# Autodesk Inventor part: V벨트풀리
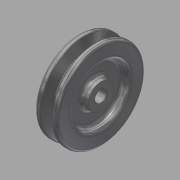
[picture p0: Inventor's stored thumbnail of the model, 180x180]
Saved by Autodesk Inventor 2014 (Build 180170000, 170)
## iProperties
Created: 2015-11
Part Number: V벨트풀리
Material: 강철, 탄소
Document SubType Name: Modeling
Designer: mduedu
Density: 7.87 g/cm^3
Mass: 415.441 g
Surface Area: 174.543 cm^2
Volume: 52.788 cm^3
Appearance: 반광택
Author: mduedu
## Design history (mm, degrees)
sketch "스케치1"
  geometry: L1 (-9.5, 0)-(9.5, 0); L2 (0, 0)-(0, 37.7); L3 (-4.825, 37.7)-(-9.5, 37.7); L4 (-9.5, 37.7)-(-9.5, 0); L5 (0, 28.7)-(-2.074, 28.7); L6 (-2.074, 28.7)-(-4.825, 37.7); L7 (4.825, 37.7)-(9.5, 37.7); L8 (9.5, 37.7)-(9.5, 0); L9 (0, 28.7)-(2.074, 28.7); L10 (2.074, 28.7)-(4.825, 37.7); L11 (-9.5, 35)-(9.5, 35); 3 further points
  constraints: 22 end point, 7 point on line, 4 perpendicular, 3 symmetric about line, 1 coincident, 1 horizontal, 1 horizontal alignment, 1 midpoint, 1 vertical
  dimensions: "d0" = 19 distance of L1.start L1.end; "d2" = 75.4 diameter of L2.end L1 (derived); "d3" = 34 deg angle of L10 L6; "d4" = 6.3 distance between parallel lines of L11 L9; "d5" = 2.7 distance between parallel lines of L7 L11; "d6" = 8 distance of point (4, 35) point (-4, 35); "d7" = 70 diameter of L11 L1
revolve "회전1" sketch "스케치1" stored, may be unused: angle "d8" = 90 deg
sketch "스케치2"
  geometry: C1 r 24 at (0, 0); C2 r 11 at (0, 0); 1 further point
  constraints: 2 centre point, 2 coincident
  dimensions: "d9" = 48 diameter of C1; "d10" = 22 diameter of C2
extrude "돌출1" cut sketch "스케치2" distance "d11" = 6; taper "d12" = 0 deg
fillet "모깎기1" dims "d13" = 3
fillet "모깎기2" dims "d14" = 3
fillet "모깎기3" dims "d15" = 1, "d16" = 0.5, "d17" = 2
hole "구멍1" diameter "d20" = 10; stored, may be unused: countersink angle "d24" = 90 deg, drill point angle "d26" = 118 deg; dims "d18" = 10, "d19" = 10, "d21" = 6, "d22" = 4, "d23" = 2, "d25" = 8
sketch "스케치3"
  geometry: L1 (-1.5, 0)-(1.5, 0); L2 (1.5, 0)-(1.5, 6.4); L3 (1.5, 6.4)-(-1.5, 6.4); L4 (-1.5, 6.4)-(-1.5, 0); 2 further points
  constraints: 8 end point, 2 parallel, 1 coincident, 1 horizontal, 1 midpoint, 1 perpendicular
  dimensions: "d27" = 3 distance of L2.end L3.end; "d29" = 6.4 distance of L3.end L1.start
extrude "돌출2" cut sketch "스케치3" stored distance "d30" = 6; taper "d31" = 0 deg
chamfer "모따기1" distance "d32" = 0.5; stored, may be unused: second distance "d33" = 2, angle "d34" = 45 deg
node "솔리드1"
mirror "대칭1"
